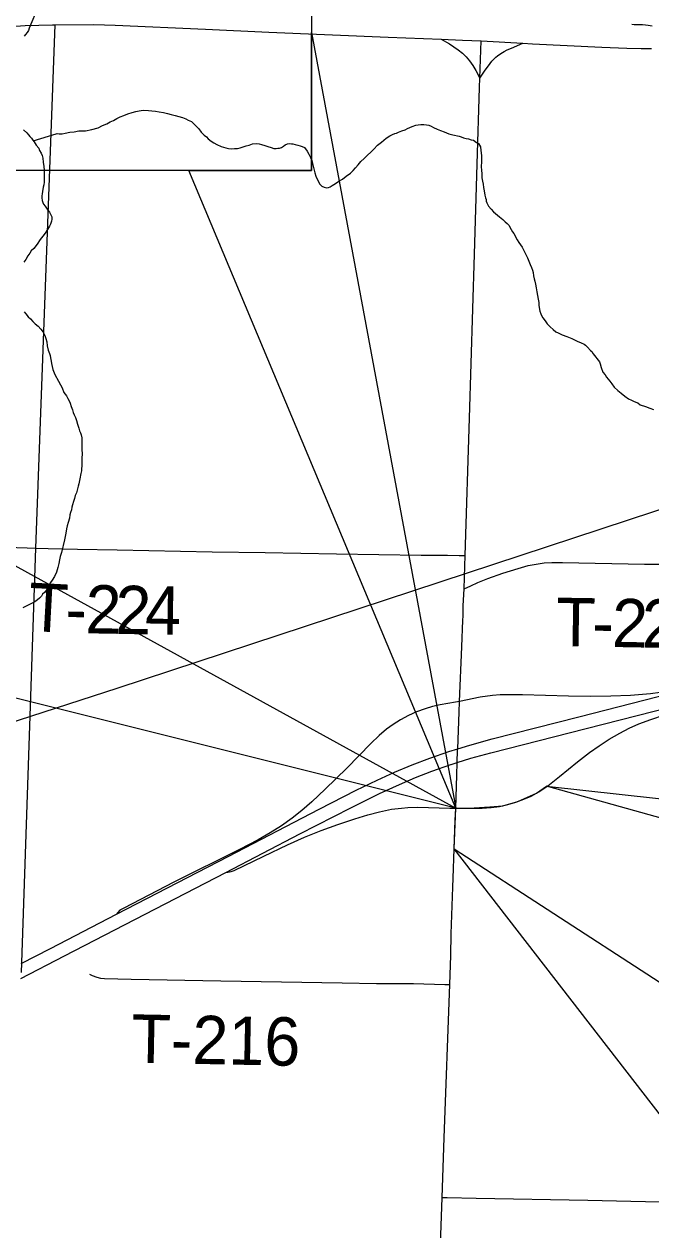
# Model space of a CAD drawing. Extents: x 0 to 64.8, y -5 to 22.
# Drawn here: x 4.674 to 5.41, y 17.005 to 18.422 of the extents above; entities that cross this region are included whole.
import ezdxf

# ---------------------------------------------------------------- set-up
doc = ezdxf.new("R2010")
doc.units = 0
for name, color, linetype in [('GM_X_City_Street', 7, 'Continuous'), ('GM_X_Corporation', 7, 'Continuous'), ('GM_X_County_Road', 7, 'Continuous'), ('GM_X_Interchange_Ramps', 7, 'Continuous'), ('GM_X_Major_River', 7, 'Continuous'), ('GM_X_Minor_River', 7, 'Continuous'), ('GM_X_Rail_Line', 7, 'Continuous'), ('GM_X_Township_Road', 7, 'Continuous'), ('GM_X_Township_Road_Text', 7, 'Continuous'), ('GM_X_US_Location', 7, 'Continuous'), ('GM_X_US_Route', 7, 'Continuous'), ('SH_Data', 7, 'Continuous'), ('SH_Masking', 7, 'Continuous'), ('SH_Text', 7, 'Continuous')]:
    doc.layers.add(name, color=color, linetype=linetype)

msp = doc.modelspace()

# ---------------------------------------------------------------- linework, layer by layer
at = {"layer": 'GM_X_City_Street'}
for points in [[(4.2488, 17.8211), (4.3713, 17.8166), (4.4706, 17.8131), (4.542, 17.8107), (4.677, 17.8063)], [(4.677, 17.8063), (4.687, 17.8059)]]:
    msp.add_lwpolyline(points, dxfattribs=at)
at = {"layer": 'GM_X_Corporation'}
msp.add_lwpolyline([(4.647, 18.418), (4.6749, 18.42), (4.707, 18.421), (4.7097, 18.421), (4.687, 17.8059), (4.6703, 17.3075)], dxfattribs=at)
at = {"layer": 'GM_X_County_Road'}
for points in [[(4.5896, 18.4125), (4.616, 18.4154), (4.647, 18.418), (4.6749, 18.42), (4.707, 18.421), (4.7097, 18.421)], [(4.7097, 18.421), (4.7556, 18.4214), (4.7806, 18.4206), (4.8864, 18.4157), (4.9611, 18.4123), (5.1012, 18.4064), (5.1633, 18.404)], [(5.1633, 18.404), (5.1884, 18.403), (5.2102, 18.4019)]]:
    msp.add_lwpolyline(points, dxfattribs=at)
at = {"layer": 'GM_X_Interchange_Ramps'}
for points in [[(5.1633, 18.404), (5.1733, 18.3984), (5.1834, 18.3914), (5.1882, 18.3877), (5.1926, 18.3834), (5.1965, 18.3786), (5.2005, 18.373), (5.204, 18.3672), (5.2088, 18.3583)], [(5.2088, 18.3583), (5.215, 18.3674), (5.2179, 18.3713), (5.221, 18.3756), (5.223, 18.3782), (5.225, 18.3804), (5.2275, 18.3827), (5.2296, 18.3845), (5.2333, 18.3871), (5.2374, 18.3897), (5.241, 18.3914), (5.246, 18.3936), (5.2592, 18.3993)], [(5.4795, 17.6475), (5.4751, 17.6477), (5.473, 17.6475), (5.4711, 17.647), (5.4491, 17.6415), (5.4318, 17.6382), (5.4091, 17.6348), (5.3855, 17.633), (5.3626, 17.6321), (5.339, 17.6318), (5.3129, 17.6322), (5.2588, 17.6339), (5.2421, 17.6339), (5.2328, 17.6336), (5.2235, 17.6328), (5.2093, 17.6309), (5.1849, 17.626)], [(5.1849, 17.626), (5.1801, 17.6252), (5.1623, 17.6222), (5.1533, 17.62), (5.1444, 17.6173), (5.1345, 17.6137), (5.1249, 17.6093), (5.1155, 17.6044), (5.1071, 17.5991), (5.0991, 17.5933), (5.0905, 17.5861), (5.0807, 17.5766), (5.0524, 17.5478), (5.0271, 17.523), (5.0113, 17.5081), (4.9996, 17.4978), (4.9884, 17.4889), (4.9758, 17.4799), (4.9626, 17.4716), (4.9486, 17.4635), (4.9266, 17.452), (4.8493, 17.4136), (4.7905, 17.3833), (4.7861, 17.3807), (4.7836, 17.3779), (4.7819, 17.376)], [(5.1804, 17.5006), (5.2116, 17.5007), (5.2221, 17.5014), (5.2319, 17.5027), (5.2417, 17.5048), (5.2512, 17.5076), (5.2605, 17.5111), (5.269, 17.5149), (5.2782, 17.52), (5.2886, 17.5269), (5.3022, 17.5378), (5.3233, 17.5551), (5.3376, 17.5661), (5.3487, 17.574), (5.3607, 17.5818), (5.3731, 17.5889), (5.3842, 17.5945), (5.3955, 17.5996), (5.4095, 17.6049), (5.4254, 17.6101)], [(4.9103, 17.4252), (4.913, 17.4255), (4.9169, 17.4261), (4.9204, 17.4273), (4.955, 17.4442), (4.983, 17.4576), (5.0029, 17.4664), (5.0225, 17.4743), (5.0418, 17.4813), (5.0618, 17.488), (5.0773, 17.4926), (5.091, 17.4963), (5.105, 17.4993), (5.1167, 17.5008), (5.1241, 17.5014), (5.1359, 17.5017), (5.1737, 17.5007), (5.1768, 17.5007), (5.1804, 17.5006)]]:
    msp.add_lwpolyline(points, dxfattribs=at)
at = {"layer": 'GM_X_Major_River'}
msp.add_lwpolyline([(5.3871, 18.4218), (5.3898, 18.4214), (5.3997, 18.4212), (5.4034, 18.4207), (5.4065, 18.4203), (5.411, 18.4198)], dxfattribs=at)
at = {"layer": 'GM_X_Minor_River'}
for points in [[(4.6901, 18.4421), (4.6794, 18.4169), (4.6786, 18.4142), (4.677, 18.412), (4.6751, 18.4094), (4.6735, 18.4075)], [(4.6841, 18.2847), (4.7112, 18.2927), (4.7124, 18.293), (4.7147, 18.2926), (4.7181, 18.2929), (4.7219, 18.2936), (4.7273, 18.2946), (4.7322, 18.2953), (4.7379, 18.2963), (4.7455, 18.2965), (4.7532, 18.2978), (4.7604, 18.2999), (4.7658, 18.3025), (4.7708, 18.3046), (4.7747, 18.3068), (4.7785, 18.3086), (4.7824, 18.3108), (4.7862, 18.3127), (4.7908, 18.3144), (4.7954, 18.3162), (4.8004, 18.318), (4.8046, 18.3191), (4.8088, 18.3197), (4.8134, 18.3204), (4.8195, 18.3203), (4.8236, 18.3198), (4.8278, 18.3193), (4.8323, 18.3185), (4.8373, 18.318), (4.8418, 18.3167), (4.8463, 18.3155), (4.8509, 18.3142), (4.8554, 18.313), (4.8596, 18.3118), (4.8633, 18.3105), (4.8664, 18.3089), (4.8701, 18.3073), (4.8787, 18.2988), (4.8816, 18.2949), (4.885, 18.2914), (4.8876, 18.2891), (4.8898, 18.2868), (4.8932, 18.284), (4.8965, 18.2821), (4.8999, 18.2801), (4.9048, 18.2781), (4.9078, 18.2772), (4.9105, 18.2764), (4.9135, 18.2756), (4.9173, 18.2751), (4.9207, 18.2754), (4.9242, 18.2754), (4.9272, 18.2764), (4.9307, 18.2775), (4.9345, 18.2785), (4.9379, 18.2796), (4.9418, 18.281), (4.9467, 18.2813), (4.9497, 18.2809), (4.9524, 18.2804), (4.9562, 18.2792), (4.9599, 18.278), (4.9637, 18.2767), (4.9667, 18.2755), (4.9694, 18.2755), (4.9717, 18.2758), (4.9736, 18.2761), (4.9759, 18.2769), (4.9782, 18.2783), (4.9801, 18.2798), (4.9828, 18.2809), (4.9855, 18.2816), (4.9874, 18.2812), (4.9893, 18.2811), (4.9919, 18.2803), (4.995, 18.2795), (4.9976, 18.2786), (5.0002, 18.2778), (5.0029, 18.2766), (5.0058, 18.2724), (5.008, 18.2689), (5.0098, 18.2651), (5.0113, 18.2616), (5.0123, 18.2578), (5.0151, 18.2471), (5.0162, 18.2429), (5.0187, 18.2371), (5.0209, 18.2337), (5.0232, 18.2313), (5.0258, 18.2301), (5.0288, 18.2293), (5.0311, 18.2296), (5.033, 18.2304), (5.0353, 18.2322), (5.0392, 18.2344), (5.0431, 18.237), (5.0473, 18.2395), (5.0519, 18.2432), (5.057, 18.2465), (5.0601, 18.2499), (5.0628, 18.2529)], [(5.0628, 18.2529), (5.0659, 18.2562), (5.0691, 18.2603), (5.0729, 18.264), (5.0768, 18.2677), (5.0807, 18.2711), (5.0842, 18.2748), (5.0885, 18.2793), (5.0931, 18.283), (5.0989, 18.2878), (5.1032, 18.2903), (5.1063, 18.2921), (5.109, 18.2932), (5.1109, 18.2936), (5.1132, 18.2947), (5.117, 18.2965), (5.1212, 18.2975), (5.1239, 18.299), (5.1266, 18.3004), (5.1293, 18.3015), (5.1335, 18.3029), (5.1362, 18.3033), (5.1396, 18.3039), (5.143, 18.3039), (5.1461, 18.3034), (5.1487, 18.303), (5.1514, 18.3018), (5.1544, 18.3002), (5.1585, 18.2982), (5.1626, 18.2966), (5.1668, 18.295), (5.1724, 18.2929), (5.177, 18.2917), (5.1845, 18.29), (5.1868, 18.2892), (5.1894, 18.288), (5.1928, 18.2872), (5.1955, 18.2871), (5.1985, 18.2859), (5.2012, 18.2855), (5.2049, 18.2827), (5.2072, 18.2815), (5.2097, 18.2777), (5.21, 18.2731), (5.2107, 18.2674), (5.2106, 18.2632), (5.2105, 18.2598), (5.2104, 18.2545), (5.2106, 18.2499), (5.2109, 18.2461), (5.2112, 18.2412), (5.2119, 18.237), (5.2126, 18.2335), (5.2132, 18.2297), (5.2139, 18.2259), (5.2146, 18.2209), (5.2152, 18.2175), (5.216, 18.2156), (5.2163, 18.2137), (5.217, 18.2118), (5.2188, 18.2079), (5.2222, 18.2044), (5.2248, 18.2013), (5.2318, 18.1951), (5.2356, 18.192), (5.2386, 18.1896), (5.2408, 18.1873), (5.243, 18.185), (5.2441, 18.183), (5.2456, 18.1804), (5.247, 18.1777), (5.2485, 18.1757), (5.2525, 18.1684), (5.2544, 18.1653), (5.2566, 18.1622), (5.2584, 18.1595), (5.2599, 18.1565), (5.2613, 18.1542), (5.2628, 18.1511), (5.2646, 18.1472), (5.2664, 18.1434), (5.2678, 18.1392), (5.2693, 18.1357), (5.2704, 18.1327), (5.2714, 18.13), (5.2717, 18.1258), (5.2724, 18.1224), (5.2735, 18.1197), (5.2742, 18.1163), (5.2748, 18.1117), (5.2755, 18.1071), (5.2765, 18.1029), (5.2772, 18.0987), (5.2779, 18.0945), (5.2782, 18.0915), (5.2785, 18.0888), (5.2792, 18.0846), (5.2802, 18.0815), (5.2813, 18.0792), (5.2828, 18.0765), (5.2854, 18.0731)], [(4.6729, 18.2973), (4.6767, 18.2938), (4.6789, 18.2915), (4.6804, 18.2896), (4.6822, 18.2876), (4.6837, 18.2853), (4.6852, 18.2834), (4.6867, 18.2815), (4.6878, 18.2795), (4.6907, 18.276), (4.6918, 18.2734), (4.6936, 18.2699), (4.6947, 18.2672), (4.6954, 18.2642), (4.696, 18.2596), (4.6967, 18.2546), (4.697, 18.2501), (4.6973, 18.2459), (4.6972, 18.2425), (4.6971, 18.239), (4.697, 18.236), (4.6966, 18.233), (4.6961, 18.23), (4.6953, 18.225), (4.6948, 18.2224), (4.6944, 18.2201), (4.6943, 18.2175), (4.6947, 18.2144), (4.6954, 18.2121), (4.6965, 18.2102), (4.6983, 18.2079), (4.6998, 18.2056), (4.7016, 18.2032), (4.7035, 18.2009), (4.7049, 18.1978), (4.706, 18.1952), (4.7063, 18.1925), (4.7059, 18.1902), (4.7047, 18.1868), (4.7035, 18.1842), (4.7011, 18.1805), (4.6984, 18.176), (4.6956, 18.1726), (4.6925, 18.1685), (4.6889, 18.1632), (4.685, 18.158), (4.6819, 18.1554), (4.6803, 18.1528), (4.678, 18.1494), (4.6756, 18.1453), (4.6733, 18.1419)], [(4.6735, 18.0838), (4.6757, 18.0815), (4.6783, 18.078), (4.6809, 18.0753), (4.6839, 18.0722), (4.6865, 18.0695), (4.6902, 18.0667), (4.6932, 18.0632), (4.6961, 18.0597), (4.6979, 18.0559), (4.699, 18.0525), (4.7001, 18.0486), (4.7007, 18.0437)], [(5.2854, 18.0731), (5.288, 18.0696), (5.2913, 18.0661), (5.2947, 18.063), (5.298, 18.0602), (5.3006, 18.059), (5.3055, 18.0567), (5.3108, 18.0546), (5.3168, 18.0522), (5.3229, 18.0494), (5.3278, 18.0474), (5.3311, 18.0458), (5.333, 18.0446), (5.3352, 18.0423), (5.3386, 18.0384), (5.3404, 18.0369), (5.3419, 18.0342), (5.3493, 18.0249), (5.35, 18.0226), (5.3511, 18.0184), (5.3532, 18.013), (5.3558, 18.0096), (5.3576, 18.0069), (5.3595, 18.0045), (5.3613, 18.0022), (5.3636, 17.9991), (5.3665, 17.9953), (5.3706, 17.9914), (5.3747, 17.9882), (5.3792, 17.9847), (5.3833, 17.9816), (5.3867, 17.98), (5.3893, 17.9788), (5.392, 17.9776), (5.3942, 17.9768), (5.3972, 17.9744), (5.4033, 17.9724), (5.4085, 17.9704), (5.4127, 17.9688)], [(4.7007, 18.0437), (4.7017, 18.0387), (4.7032, 18.0349), (4.7042, 18.0322), (4.7046, 18.0295), (4.7052, 18.0257), (4.7059, 18.0231), (4.7066, 18.0196), (4.7073, 18.0158), (4.7087, 18.012), (4.7098, 18.01), (4.7138, 18.0024), (4.7164, 17.9981), (4.7182, 17.9943), (4.7204, 17.9889), (4.7233, 17.985), (4.7248, 17.982), (4.7263, 17.9793), (4.7277, 17.9762), (4.7288, 17.9724), (4.7302, 17.9686), (4.7313, 17.9655), (4.7323, 17.9628), (4.7338, 17.9597), (4.7349, 17.9559), (4.7363, 17.9517), (4.7377, 17.9471), (4.7388, 17.944), (4.7399, 17.9417), (4.7406, 17.9391), (4.7412, 17.9356), (4.7415, 17.9318), (4.7414, 17.9273), (4.7413, 17.922), (4.7416, 17.917), (4.7415, 17.9117), (4.7413, 17.9052), (4.7408, 17.8969), (4.7403, 17.8939), (4.7399, 17.892), (4.7394, 17.8893), (4.7386, 17.8855), (4.7378, 17.8818), (4.7369, 17.8787), (4.7361, 17.8757), (4.7349, 17.8712), (4.7336, 17.8678), (4.7328, 17.8644), (4.7316, 17.861), (4.7303, 17.8569), (4.7295, 17.8542), (4.7291, 17.8512), (4.7282, 17.8478), (4.7274, 17.8451), (4.727, 17.8414), (4.7253, 17.8361), (4.7241, 17.8323), (4.7233, 17.8289), (4.7224, 17.8236), (4.7211, 17.816), (4.7173, 17.8009), (4.7161, 17.7964), (4.7152, 17.7922), (4.7144, 17.7881), (4.7131, 17.7832), (4.7115, 17.7779), (4.7091, 17.7726), (4.7067, 17.7685), (4.7047, 17.7659), (4.7027, 17.7621), (4.7008, 17.758), (4.6976, 17.7539), (4.6953, 17.752), (4.6941, 17.7498), (4.6918, 17.7475), (4.6891, 17.7453), (4.686, 17.7431), (4.6813, 17.7406), (4.6767, 17.7384), (4.6721, 17.7358)]]:
    msp.add_lwpolyline(points, dxfattribs=at)
at = {"layer": 'GM_X_Rail_Line'}
msp.add_lwpolyline([(4.2913, 17.4823), (4.783, 17.6416), (5.7936, 17.9743), (6.8537, 18.3208), (7.9347, 18.672), (8.7178, 18.9261), (8.9, 18.9851)], dxfattribs=at)
at = {"layer": 'GM_X_Township_Road'}
for points in [[(4.687, 17.8059), (4.702, 17.8055), (4.7361, 17.8049), (4.7827, 17.804), (4.8944, 17.8019), (4.9565, 17.8011), (5.0403, 17.7994), (5.1397, 17.7979), (5.1707, 17.7977), (5.1845, 17.7975), (5.1916, 17.7975)], [(5.1902, 17.7583), (5.198, 17.7619), (5.2065, 17.7658), (5.218, 17.7705), (5.2357, 17.7766), (5.2536, 17.7822), (5.2656, 17.7855), (5.2748, 17.7874), (5.2841, 17.7887), (5.2934, 17.7893), (5.3059, 17.7894), (5.4023, 17.7874), (5.4614, 17.7871), (5.5267, 17.7875), (5.5609, 17.7878), (5.6417, 17.7882), (5.6588, 17.7884), (5.6627, 17.7886), (5.6666, 17.7894), (5.6714, 17.792), (5.6742, 17.794)], [(4.7502, 17.3058), (4.7536, 17.3039), (4.7589, 17.3022), (4.7633, 17.3011), (4.7678, 17.3004), (4.7992, 17.2996), (4.9045, 17.2976), (5.0471, 17.2954), (5.0874, 17.2948), (5.1308, 17.2945), (5.1678, 17.2935), (5.1736, 17.2933)], [(5.1644, 17.0434), (5.1703, 17.0432), (5.2045, 17.0424), (5.3355, 17.0402), (5.4539, 17.0373), (5.5568, 17.0351), (5.6253, 17.0342), (5.6409, 17.0344), (5.6534, 17.0351), (5.6616, 17.036)]]:
    msp.add_lwpolyline(points, dxfattribs=at)
at = {"layer": 'GM_X_US_Route'}
for points in [[(5.1888, 17.7215), (5.189, 17.7262), (5.1893, 17.7384), (5.1902, 17.7583), (5.1912, 17.7848), (5.1916, 17.7975), (5.1965, 17.9588), (5.2024, 18.1515), (5.2057, 18.2572), (5.2084, 18.3473), (5.2088, 18.3583), (5.2102, 18.4019)], [(5.2102, 18.4019), (5.2592, 18.3993), (5.2707, 18.3987), (5.352, 18.3946), (5.3814, 18.3934), (5.3982, 18.3932), (5.4105, 18.3932)], [(5.1817, 17.5394), (5.1822, 17.5542), (5.1827, 17.5686), (5.1828, 17.5703), (5.1844, 17.6133), (5.1849, 17.626), (5.1875, 17.6903), (5.1888, 17.7215)], [(4.6701, 17.318), (4.7045, 17.3359), (4.7819, 17.376), (4.9132, 17.444), (5.0202, 17.4995), (5.0634, 17.5217), (5.088, 17.5336), (5.1084, 17.5429), (5.1291, 17.5515), (5.1501, 17.5595), (5.1724, 17.5671), (5.1828, 17.5703), (5.1968, 17.5746), (5.2232, 17.5819), (5.325, 17.608), (5.4792, 17.6475)], [(5.1751, 17.552), (5.1822, 17.5542), (5.1982, 17.5593), (5.2215, 17.5658), (5.3336, 17.5943), (5.4534, 17.6249)], [(4.6697, 17.3005), (4.7209, 17.3272), (4.9103, 17.4252), (4.9975, 17.4703), (5.0572, 17.501), (5.0911, 17.518), (5.1143, 17.5286), (5.1331, 17.5366), (5.1522, 17.544), (5.1745, 17.5518), (5.1751, 17.552)], [(5.1776, 17.4185), (5.1787, 17.453), (5.1799, 17.4865), (5.1804, 17.5006), (5.1813, 17.5263), (5.1817, 17.5394)], [(5.1745, 17.3274), (5.1752, 17.353), (5.1772, 17.4077), (5.1776, 17.4185)], [(5.1736, 17.2933), (5.1745, 17.3274)], [(5.1206, 15.8012), (5.1266, 15.9917), (5.1356, 16.2403), (5.1372, 16.2867), (5.1406, 16.3833), (5.1459, 16.5324), (5.1541, 16.7531), (5.1604, 16.9333), (5.1644, 17.0434), (5.1669, 17.1135), (5.1736, 17.2933)]]:
    msp.add_lwpolyline(points, dxfattribs=at)
at = {"layer": 'SH_Data'}
msp.add_lwpolyline([(5.1787, 17.453), (5.1804, 17.5006), (5.196, 17.5007), (5.2203, 17.502), (5.2356, 17.5035), (5.2535, 17.5085), (5.2753, 17.5184), (5.2869, 17.5263)], dxfattribs=at)
at = {"layer": 'SH_Masking'}
msp.add_lwpolyline([(2.9386, 18.7399), (5.0112, 18.7399), (5.0112, 18.2499), (2.9386, 18.2499)], close=True, dxfattribs=at)
at = {"layer": 'SH_Text'}
for p, q in [((5.0112, 18.2499), (5.0112, 18.4117)), ((4.8669, 18.2499), (5.0112, 18.2499)), ((6.1118, 17.2975), (5.2869, 17.5263))]:
    msp.add_line(p, q, dxfattribs=at)
msp.add_lwpolyline([(2.9386, 18.7399), (5.0112, 18.7399), (5.0112, 18.2499), (2.9386, 18.2499)], close=True, dxfattribs=at)
for points in [[(5.0112, 18.4117), (5.1804, 17.5006), (4.8669, 18.2499)], [(4.6267, 17.8051), (5.1804, 17.5006), (4.4976, 17.6713)], [(5.2869, 17.5263), (6.1118, 17.4358)], [(5.5177, 17.0152), (5.1787, 17.453), (5.6467, 17.149)]]:
    msp.add_lwpolyline(points, dxfattribs=at)

# ---------------------------------------------------------------- texts
at = {"layer": 'GM_X_Township_Road_Text'}
for s, height, rotation, p in [('T', 0.0568, 356.9085, (4.6772, 17.709)), ('2', 0.0568, 358.9375, (4.7452, 17.7061)), ('2', 0.0568, 359.0502, (4.7803, 17.7054)), ('4', 0.0568, 359.0757, (4.8153, 17.7048)), ('T', 0.0568, 359.0755, (5.2979, 17.6912)), ('2', 0.0568, 358.9388, (5.3635, 17.69)), ('2', 0.0568, 359.485, (5.3988, 17.6894)), ('-', 0.0568, 358.6446, (4.7215, 17.7066)), ('-', 0.0568, 358.8579, (5.3403, 17.6905)), ('T-216', 0.05682, 358.8762, (4.799, 17.2017))]:
    msp.add_text(s, height=height, rotation=rotation, dxfattribs=at).set_placement(p)
at = {"layer": 'GM_X_US_Location'}
for s in ['/', '0']:
    msp.add_text(s, height=0.000189, dxfattribs=at).set_placement((5.2058, 18.2264))
msp.add_text('127', height=0.000189, rotation=0, dxfattribs=at).set_placement((5.1476, 18.1872))

doc.saveas('drawing.dxf')
